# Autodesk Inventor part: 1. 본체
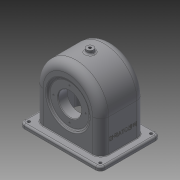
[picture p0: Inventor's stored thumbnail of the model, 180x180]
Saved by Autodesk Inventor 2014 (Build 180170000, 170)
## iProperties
Created: 2016-01
Part Number: 1. 본체
Material: 일반
Document SubType Name: Modeling
Designer: Owner
Density: 1 g/cm^3
Appearance: 기본값
Author: Owner
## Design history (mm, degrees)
sketch "스케치1"
  geometry: L1 (-57, 0)-(-57, -64); L2 (-57, -64)-(57, -64); L3 (57, -64)-(57, 0); L4 (51, 0)-(51, -64); L5 (-51, -64)-(-51, 0); A1 r 57 centre (0, 0) between (57, 0) and (-57, 0); A2 r 51 centre (0, 0) between (51, 0) and (-51, 0); 2 further points
  constraints: 10 end point, 4 point on circle, 3 vertical, 2 centre point, 2 perpendicular, 2 point on line, 2 tangent, 1 coincident, 1 midpoint, 1 parallel, 1 vertical alignment
  dimensions: "d1" = 114 diameter of A1; "d2" = 64 distance from line of L2 point (0, 0); "d3" = 6 radial gap between concentric circles of A1 A2; "d4" = 6 distance of L4.end L2.end
extrude "돌출1" new body sketch "스케치1" stored distance "d5" = 77; taper "d6" = 0 deg
extrude "돌출2" cut sketch "스케치1" stored distance "d7" = 67; taper "d8" = 0 deg
sketch "스케치2"
  geometry: L1 (-64, -33.5)-(-64, 33.5) reference; L2 (0, 38.5)-(-64, 38.5) reference; L3 (-64, -38.5)-(0, -38.5) reference; L4 (-4, 38.5)-(-4, -38.5); L5 (57, 38.5)-(0, 38.5) reference; L6 (51, 33.5)-(0, 33.5) reference; L7 (16, 19.5)-(24, 19.5); L8 (24, 19.5)-(35.747, 33.5); L9 (33.416, 38.5)-(30.899, 35.5); L10 (30.899, 35.5)-(16, 35.5); L11 (16, 35.5)-(16, 19.5); L12 (33.416, 38.5)-(35.747, 33.5); L13 (16, 35.5)-(16, 38.5); 1 further point
  constraints: 16 end point, 5 point on line, 3 parallel, 2 perpendicular, 1 collinear
  dimensions: "d9" = 60 distance between parallel lines of L1 L4; "d10" = 50 deg angle of L7 L8; "d12" = 16 distance of L7.start L10.end; "d13" = 5 distance between parallel lines of L9 L8; "d14" = 40 diameter of L11 L4; "d15" = 56 diameter of L7.end L4; "d16" = 3 distance from line of L5 L10.end
revolve "회전1" stored, may be unused: angle "d17" = 90 deg
revolve "회전2" stored, may be unused: angle "d18" = 90 deg
sketch "스케치3"
  geometry: L1 (-57, -64)-(57, -64) reference; C1 r 31 at (0, -4); C2 r 20 at (0, -4); A1 r 57 centre (0, 0) between (57, 0) and (-57, 0) reference
  constraints: 2 centre point, 1 coincident, 1 vertical alignment
  dimensions: "d19" = 62 diameter of C1; "d20" = 60 distance from line of L1 C1.centre; "d21" = 40 diameter of C2
extrude "돌출3" join sketch "스케치3" distance "d22" = 10; taper "d23" = 0 deg
extrude "돌출4" cut sketch "스케치3" stored distance "d24" = 10; taper "d25" = 0 deg
fillet "모깎기1" dims "d26" = 9
fillet "모깎기2" dims "d27" = 14
sketch "스케치4"
  geometry: C1 r 20 at (0, 0) reference; 2 further points
  constraints: 1 vertical alignment
  dimensions: "d28" = 24 distance of C1.centre point (0, 24)
hole "구멍1" sketch "스케치4" at (0, 24) diameter "d29" = 2.459; stored, may be unused: countersink angle "d33" = 90 deg, drill point angle "d35" = 118 deg; dims "d30" = 6, "d31" = 4, "d32" = 2, "d34" = 8
sketch "스케치5"
  geometry: C1 r 34.899 at (0, 0) reference; 2 further points
  constraints: 1 vertical alignment
  dimensions: "d39" = 28 distance of C1.centre point (0, 28)
hole "구멍2" sketch "스케치5" at (0, 28) diameter "d40" = 2.459; stored, may be unused: countersink angle "d44" = 90 deg, drill point angle "d46" = 118 deg; dims "d41" = 7, "d42" = 4, "d43" = 2, "d45" = 9
node "작업 평면1"
sketch "스케치6"
  geometry: L1 (-42, 33.5)-(42, 33.5) reference; L2 (-51, -24.5)-(-51, 24.5) reference; L3 (42, -33.5)-(-42, -33.5) reference; L4 (51, 24.5)-(51, -24.5) reference; L5 (-70, -52)-(70, -52); L6 (70, -52)-(70, 52); L7 (70, 52)-(-70, 52); L8 (-70, 52)-(-70, -52); L9 (-70, -52)-(70, 52); L10 (70, -52)-(-70, 52); A1 r 9 centre (-42, 24.5) between (-42, 33.5) and (-51, 24.5) reference; A2 r 9 centre (-42, -24.5) between (-51, -24.5) and (-42, -33.5) reference; A3 r 9 centre (42, -24.5) between (42, -33.5) and (51, -24.5) reference; A4 r 9 centre (42, 24.5) between (51, 24.5) and (42, 33.5) reference; 1 further point
  constraints: 12 end point, 2 midpoint, 2 parallel, 1 horizontal, 1 perpendicular
  dimensions: "d51" = 140 distance of L7.end L6.end; "d52" = 104 distance of L6.end L5.end
extrude "돌출5" join sketch "스케치6" distance "d53" = 7; taper "d54" = 0 deg
fillet "모깎기3" dims "d55" = 1
sketch "스케치7"
  geometry: L1 (70, 52)-(-70, 52) reference; L2 (-70, 52)-(-70, -52) reference; L3 (-70, -52)-(70, -52) reference; 5 further points
  constraints: 2 horizontal alignment, 2 vertical alignment
  dimensions: "d56" = 8 distance from line of L1 point (-62, 44); "d57" = 8 distance from line of point (-62, 44) L2; "d58" = 124 distance of point (62, 44) point (-62, 44); "d59" = 8 distance from line of L3 point (-62, -44)
hole "구멍3" sketch "스케치7" at (-62, 44), (62, 44), (62, -44), (-62, -44) diameter "d60" = 5; stored, may be unused: countersink angle "d64" = 90 deg, drill point angle "d66" = 118 deg; dims "d61" = 7, "d62" = 4, "d63" = 2, "d65" = 9
fillet "모깎기4" dims "d67" = 8
fillet "모깎기5" dims "d68" = 3
fillet "모깎기6" dims "d69" = 3
node "작업 평면2"
sketch "스케치8"
  geometry: C1 r 6 at (0, 0); 1 further point
  constraints: 1 centre point, 1 coincident
  dimensions: "d71" = 12 diameter of C1
extrude "돌출6" join sketch "스케치8" stored distance "d72" = 7; taper "d73" = 0 deg
hole "구멍4" diameter "d76" = 4.459; stored, may be unused: countersink angle "d80" = 90 deg, drill point angle "d82" = 118 deg; dims "d77" = 7, "d78" = 4, "d79" = 2, "d81" = 9, "d96" = 10, "d97" = 10
fillet "모깎기7" dims "d83" = 3
chamfer "모따기1" distance "d84" = 1; stored, may be unused: second distance "d85" = 2, angle "d86" = 45 deg
chamfer "모따기2" distance "d87" = 1; stored, may be unused: second distance "d88" = 2, angle "d89" = 45 deg
fillet "모깎기8" dims "d90" = 3
fillet "모깎기9" dims "d91" = 3
sketch "스케치9"
  geometry: L1 (-14, 0)-(-14, -56) reference; L2 (68.5, -64)-(-19.5, -64) reference; 2 further points
  constraints: 1 other
  dimensions: "d92" = 38.5 distance from line of L1 point (24.5, -34); "d93" = 30 distance from line of L2 point (24.5, -34)
feature "엠보싱1" sketch "스케치9" dims "d1" = 114, "d2" = 64, "d3" = 6, "d4" = 6, "d94" = 0.5, "d95" = 0
node "솔리드1"
pattern_circular "원형 패턴1" dims angle "d37" = 360 deg
pattern_circular "원형 패턴2" dims angle "d48" = 360 deg
other parameters: "d50" = -64, "d70" = 63
